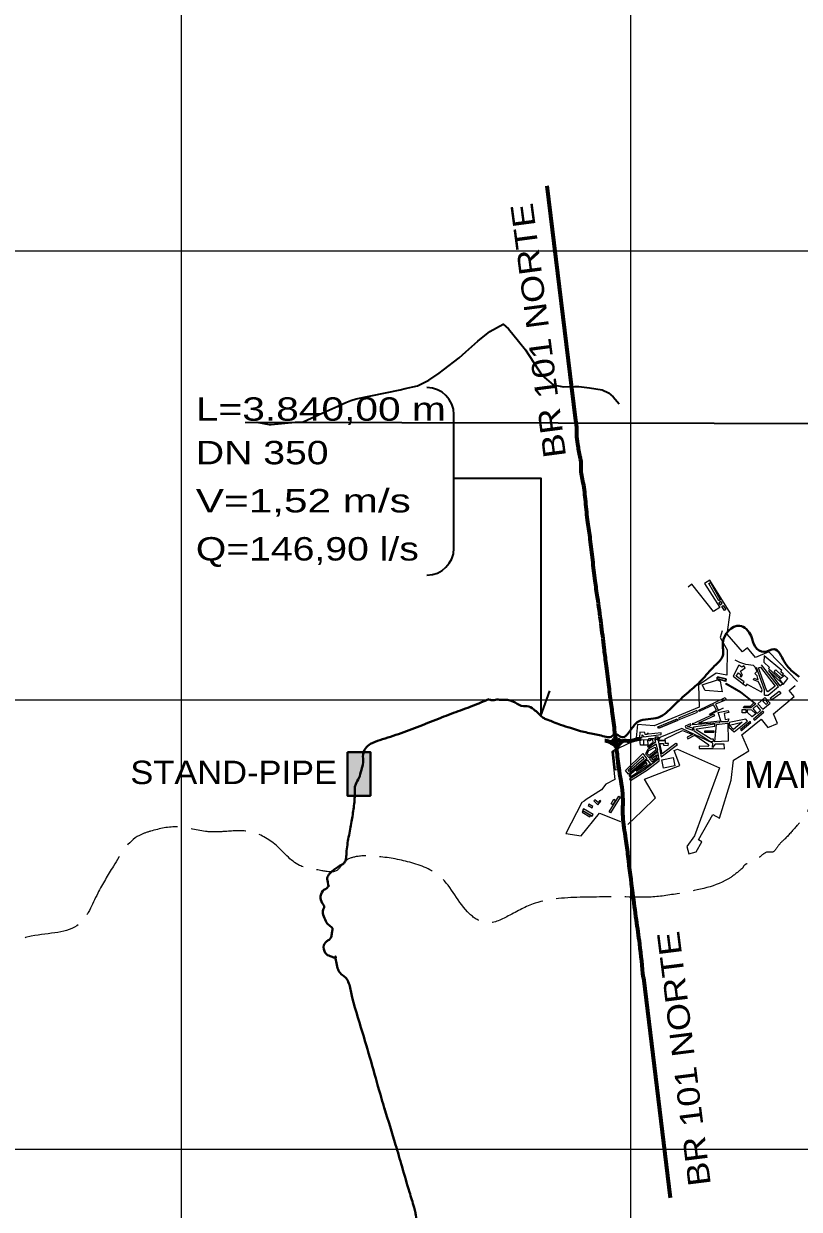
# Model space of a CAD drawing. Extents: x 0 to 1772, y 0 to 1188.
# Drawn here: x 975.1 to 1085.1, y 181.7 to 349.8 of the extents above; entities that cross this region are included whole.
import ezdxf

# ---------------------------------------------------------------- set-up
doc = ezdxf.new("R2010")
doc.units = 0
doc.header["$LTSCALE"] = 1.3
doc.linetypes.add('DOT_DASHED', pattern=[7.7, 5, -1.2, 0.3, -1.2])
doc.linetypes.add('LONG_DASHED', pattern=[7.5, 6, -1.5])
for name, color, linetype, lineweight in [('1', 7, 'DOT_DASHED', 13), ('3', 7, 'Continuous', 35), ('4', 7, 'Continuous', 13), ('5', 7, 'LONG_DASHED', 25), ('6', 7, 'Continuous', 40), ('63', 7, 'Continuous', 25), ('8', 7, 'Continuous', 35), ('9', 7, 'Continuous', 40)]:
    doc.layers.add(name, color=color, linetype=linetype, lineweight=lineweight)

msp = doc.modelspace()

# ---------------------------------------------------------------- hatches: boundary and pattern name
at = {"layer": '8'}
msp.add_hatch(color=256, dxfattribs=at).paths.add_polyline_path([(1021.023, 246.501), (1024.288, 246.501), (1024.288, 240.322), (1021.023, 240.322)])

# ---------------------------------------------------------------- linework, layer by layer
at = {"layer": '1', "linetype": 'Continuous'}
for p, q in [((1061.503, 248.025), (1059.413, 247.021)), ((1063.076, 247.499), (1062.565, 247.489)), ((1063.077, 247.49), (1063.066, 248.276))]:
    msp.add_line(p, q, dxfattribs=at)
for points in [[(1084.845, 256.515), (1080.766, 260.748), (1078.897, 259.943), (1077.745, 261.289), (1077.072, 260.713), (1074.895, 263.256), (1075.311, 266.276), (1072.428, 270.913), (1071.673, 270.444), (1073.816, 266.997), (1072.925, 266.443), (1069.86, 270.331), (1069.322, 269.907)], [(1074.171, 263.701), (1073.899, 262.776), (1074.877, 261.005), (1074.813, 257.409), (1073.315, 257.704), (1070.801, 255.998), (1070.91, 252.877), (1064.512, 250.229), (1062.144, 250.422), (1061.99, 248.528)], [(1079.72, 255.025), (1079.838, 255.321), (1079.338, 256.468), (1078.592, 256.773), (1078.689, 257.009), (1079.277, 256.769), (1079.111, 257.307), (1078.779, 257.649), (1079.121, 257.981), (1078.811, 258.62), (1078.586, 258.773), (1077.522, 258.923), (1076.694, 259.193), (1075.995, 259.546)], [(1079.72, 255.025), (1077.677, 256.124), (1077.547, 255.881), (1077.078, 256.133), (1077.263, 256.478), (1076.14, 257.277), (1076.471, 257.742), (1076.767, 257.532), (1076.73, 257.22), (1076.877, 257.202), (1077.072, 257.433), (1076.787, 257.964), (1077.434, 258.474), (1077.222, 258.743), (1076.953, 258.531), (1076.513, 258.826), (1075.727, 257.276), (1077.134, 256.205)], [(1080.178, 254.599), (1080.176, 255.332), (1079.029, 258.521)], [(1080.178, 254.599), (1080.706, 254.601), (1082.145, 255.826), (1079.732, 258.906)], [(1060.791, 236.222), (1060.791, 236.222), (1062.754, 238.124), (1064.717, 240.026), (1063.139, 242.666), (1068.167, 244.602), (1067.354, 246.715), (1067.838, 246.901), (1073.783, 244.253), (1070.229, 234.608), (1069.175, 233.101), (1069.451, 232.077), (1070.475, 232.353), (1071.289, 233.791), (1070.803, 234.066), (1072.838, 237.661), (1073.765, 237.137), (1075.461, 242.516), (1075.76, 245.352), (1077.94, 246.691), (1076.977, 248.977), (1079.701, 251.172), (1080.631, 250.017), (1081.989, 250.564), (1081.443, 251.922), (1084.367, 254.397), (1083.652, 255.241), (1084.496, 255.955)], [(1059.065, 246.87), (1058.542, 246.544), (1058.928, 242.628), (1057.684, 241.951), (1057.063, 241.176), (1054.899, 239.772), (1054.583, 239.567), (1054.267, 239.362), (1052.023, 234.949), (1054.192, 234.631), (1056.774, 237.832), (1059.743, 236.643)]]:
    msp.add_lwpolyline(points, dxfattribs=at)
for points in [[(1072.492, 270.562), (1073.901, 268.105), (1073.678, 267.977), (1072.269, 270.434)], [(1074.167, 267.618), (1073.963, 267.882), (1073.699, 267.678), (1073.903, 267.414)], [(1074.33, 267.313), (1074.698, 266.745), (1074.489, 266.61), (1074.122, 267.179)], [(1082.626, 258.064), (1080.141, 260.172), (1080.083, 259.277), (1080.898, 258.527), (1080.741, 258.357), (1082.245, 256.973), (1082.384, 257.124), (1081.538, 257.903), (1081.772, 258.157), (1082.669, 257.332), (1082.872, 257.553), (1082.499, 257.896)], [(1080.461, 255.292), (1079.334, 258.481), (1079.582, 258.569), (1081.678, 255.865), (1080.653, 255.071)], [(1080.757, 258.059), (1082.348, 255.908), (1082.733, 256.192)], [(1083.014, 257.353), (1082.305, 256.823), (1082.836, 256.113), (1083.483, 256.928)], [(1074.175, 255.056), (1071.772, 255.243), (1071.323, 256.056), (1073.492, 256.761), (1073.88, 256.549)], [(1074.692, 256.916), (1073.498, 257.194), (1073.44, 256.944), (1074.634, 256.667)], [(1073.451, 256.846), (1073.45, 257.146), (1074.731, 256.915), (1074.664, 256.542)], [(1077.278, 253.011), (1078.192, 253.014), (1078.635, 253.486), (1076.789, 254.92), (1074.668, 256.143), (1074.753, 256.29), (1076.785, 255.118), (1078.949, 253.33), (1078.219, 252.779), (1077.174, 252.789)], [(1072.381, 251.898), (1072.381, 251.898), (1073.36, 252.463), (1072.938, 253.193), (1070.917, 252.286), (1070.847, 252.442), (1074.569, 254.272), (1074.75, 253.905), (1073.239, 253.313), (1073.576, 252.454), (1074.301, 252.738), (1072.421, 251.78)], [(1080.959, 253.446), (1080.2, 254.263), (1079.235, 253.367), (1079.954, 252.592)], [(1081.196, 253.911), (1080.992, 254.175), (1082.237, 255.137), (1082.482, 254.821)], [(1068.087, 251.11), (1070.658, 252.172), (1070.568, 252.389), (1067.997, 251.327)], [(1074.959, 250.807), (1074.005, 250.804), (1073.609, 252.111), (1075.032, 252.403), (1075.092, 252.111), (1074.429, 251.975), (1074.605, 251.114), (1075.11, 251.218)], [(1077.018, 252.068), (1077.016, 252.552), (1077.501, 252.554), (1077.502, 252.069)], [(1078.421, 251.525), (1077.737, 252.144), (1077.773, 252.554), (1078.346, 252.504), (1078.916, 251.937)], [(1079.127, 251.987), (1078.542, 252.706), (1079.04, 253.111), (1079.621, 252.397)], [(1078.745, 251.042), (1080.069, 252.189), (1079.946, 252.331), (1078.622, 251.184)], [(1080.426, 253.27), (1079.928, 253.753), (1080.275, 253.903), (1080.649, 253.519)], [(1067.876, 250.969), (1065.142, 249.859), (1065.039, 250.113), (1067.773, 251.223)], [(1067.838, 250.987), (1065.204, 249.907), (1065.117, 250.119), (1067.751, 251.2)], [(1069.961, 250.506), (1072.952, 251.897), (1073.071, 251.641), (1070.808, 250.588), (1073.821, 250.963), (1073.781, 250.658), (1070.023, 250.352), (1070.002, 250.605)], [(1073.128, 247.969), (1073.344, 250.41), (1074.989, 250.598), (1074.997, 248.056)], [(1075.125, 250.037), (1075.884, 249.381), (1077.741, 250.89), (1077.525, 251.156), (1075.136, 250.696)], [(1075.796, 249.704), (1075.211, 250.336), (1077.022, 250.776)], [(1077, 249.646), (1078.25, 250.705), (1078.119, 250.86), (1076.742, 249.694), (1076.895, 249.514)], [(1065.503, 249), (1065.503, 249.247), (1063.731, 249.036), (1063.717, 249.154), (1063.514, 249.13), (1063.528, 249.018), (1063.235, 248.983), (1063.2, 249.276), (1062.469, 249.313), (1062.432, 248.582), (1062.819, 248.562), (1062.839, 248.949), (1063.015, 248.786), (1063.015, 248.654)], [(1074.462, 247.614), (1073.175, 247.611), (1072.802, 247.141), (1072.847, 247.774), (1068.441, 249.869), (1065.332, 248.595), (1065.053, 248.149), (1066.106, 248.105), (1066.106, 248.105), (1066.105, 248.386), (1066.105, 248.386), (1068.536, 249.565), (1069.965, 249.007), (1069.194, 248.606), (1069.314, 248.374), (1070.306, 248.89), (1072.286, 247.538), (1072.137, 247.319), (1070.906, 247.346), (1070.899, 247.04), (1072.876, 246.996), (1074.508, 246.959)], [(1069.986, 249.611), (1069.985, 249.882), (1069.267, 250.113), (1069.771, 250.347), (1069.682, 250.538), (1068.906, 250.177), (1069.011, 249.952)], [(1072.936, 248.048), (1072.935, 248.359), (1072.625, 248.358), (1070.49, 249.651), (1070.591, 249.818), (1073.143, 250.163), (1073.104, 250.454), (1070.105, 250.049), (1070.169, 249.574), (1072.471, 248.027)], [(1071.719, 249.527), (1073.006, 249.531), (1073.006, 249.297), (1071.719, 249.293)], [(1062.565, 247.489), (1062.481, 248.256), (1063.585, 248.293), (1063.611, 247.491)], [(1065.03, 246.781), (1064.818, 247.653), (1063.642, 246.875), (1063.3, 246.247), (1063.768, 245.745)], [(1064.772, 246.768), (1063.792, 246.003), (1063.544, 246.321), (1063.777, 246.74), (1064.648, 247.222)], [(1063.773, 248.103), (1063.772, 248.414), (1064.568, 248.416), (1064.704, 247.92), (1063.704, 247.152), (1063.575, 247.319), (1064.368, 247.928), (1064.331, 248.24), (1063.967, 248.24), (1063.967, 248.087), (1063.758, 248.087)], [(1064.838, 248.206), (1064.68, 248.651), (1065.125, 248.652)], [(1067.815, 247.563), (1067.617, 247.744), (1065.668, 246.244), (1065.351, 247.745), (1065.87, 247.722), (1065.86, 247.492), (1066.528, 247.462), (1066.54, 247.732), (1066.134, 247.75), (1066.153, 248.156), (1065.097, 248.203), (1065.496, 245.823)], [(1059.022, 243.961), (1058.781, 246.553), (1059.039, 246.577), (1059.28, 243.985)], [(1060.878, 243.364), (1060.483, 243.903), (1062.895, 246.332), (1063.462, 245.572)], [(1060.975, 243.745), (1060.839, 243.941), (1062.908, 245.89), (1063.044, 245.558)], [(1065.231, 245.282), (1065.23, 245.585), (1063.086, 243.96), (1061.039, 242.676), (1061.163, 242.478), (1063.597, 244.006)], [(1065.205, 245.761), (1065.055, 246.56), (1063.879, 245.573), (1064.245, 245.137)], [(1064.861, 245.748), (1064.371, 245.378), (1064.212, 245.588), (1064.908, 246.113)], [(1065.864, 244.223), (1065.621, 245.403), (1067.205, 245.728), (1067.447, 244.549)], [(1063.548, 245.4), (1063.992, 244.799), (1061.161, 242.959), (1060.996, 243.213)], [(1061.994, 243.81), (1063.538, 244.773), (1063.367, 245.047)], [(1055.156, 238.928), (1055.723, 238.593), (1055.844, 238.798), (1055.276, 239.133)], [(1055.98, 239.581), (1056.556, 239.025), (1056.967, 239.546), (1056.823, 239.66), (1056.576, 239.347), (1056.099, 239.723)], [(1058.14, 238.033), (1059.498, 240.244), (1059.707, 240.116), (1058.349, 237.905)], [(1058.409, 239.148), (1058.785, 239.821), (1059.022, 239.689), (1058.646, 239.016)], [(1054.297, 237.979), (1055.412, 237.31), (1055.526, 237.498), (1054.411, 238.168)], [(1055.852, 237.648), (1054.485, 238.442), (1054.362, 238.23), (1055.729, 237.436)]]:
    msp.add_lwpolyline(points, close=True, dxfattribs=at)
at = {"layer": '3'}
for points in [[(1139.418, 292.958), (1006.614, 293.247), (1008.192, 293.315), (1009.946, 292.988), (1010.201, 292.983), (1013.605, 293.316), (1014.771, 293.369), (1017.552, 294.641), (1019.654, 295.559), (1020.812, 296.089), (1021.528, 296.357), (1022.255, 296.595), (1028.496, 297.874), (1029.236, 298.067), (1030.977, 298.455), (1032.573, 299.254), (1034.033, 300.279), (1034.654, 300.724), (1036.861, 302.453), (1037.829, 303.282), (1039.544, 304.804), (1041.226, 306.17), (1043.119, 307.223), (1043.865, 306.529), (1045.279, 304.788), (1046.297, 303.579), (1048.63, 299.928)], [(1139.418, 292.958), (1006.614, 293.247), (1008.192, 293.315), (1009.946, 292.988), (1010.201, 292.983), (1013.605, 293.316), (1014.771, 293.369), (1017.552, 294.641), (1019.654, 295.559), (1020.812, 296.089), (1021.528, 296.357), (1022.255, 296.595), (1028.496, 297.874), (1029.236, 298.067), (1030.977, 298.455), (1032.573, 299.254), (1034.033, 300.279), (1034.654, 300.724), (1036.861, 302.453), (1037.829, 303.282), (1039.544, 304.804), (1041.226, 306.17), (1043.119, 307.223), (1043.865, 306.529), (1045.279, 304.788), (1046.297, 303.579), (1048.63, 299.928)], [(1048.63, 299.928), (1050.182, 298.607), (1051.686, 298.33), (1053.214, 298.386), (1053.85, 298.353), (1055.371, 298.196), (1057.131, 297.904), (1058.048, 297.458), (1058.732, 296.886), (1059.569, 295.925)], [(1048.63, 299.928), (1050.182, 298.607), (1051.686, 298.33), (1053.214, 298.386), (1053.85, 298.353), (1055.371, 298.196), (1057.131, 297.904), (1058.048, 297.458), (1058.732, 296.886), (1059.569, 295.925)]]:
    msp.add_lwpolyline(points, dxfattribs=at)
at = {"layer": '4', "lineweight": 70}
for p, q in [((1053.374, 293.92), (1049.343, 326.851)), ((1062.992, 214.486), (1066.783, 183.302))]:
    msp.add_line(p, q, dxfattribs=at)
for points in [[(1059.249, 246.974), (1058.922, 249.644), (1058.59, 252.299), (1058.417, 253.395), (1058.1, 256.112), (1057.706, 259.091), (1057.437, 261.298), (1057.008, 264.756), (1056.496, 268.489), (1056.155, 270.801), (1055.812, 273.781), (1055.47, 276.706), (1055.129, 279.102), (1054.814, 282.027), (1054.472, 284.701), (1054.159, 286.762), (1054.156, 287.778), (1054.019, 288.375), (1053.721, 290.194), (1053.541, 291.596), (1053.538, 292.612), (1053.374, 293.92)], [(1059.245, 246.912), (1059.083, 247.313), (1058.526, 247.744), (1058.094, 247.989), (1057.547, 248.109)], [(1058.246, 247.93), (1058.759, 248.175), (1059.046, 248.627)], [(1059.943, 247.986), (1059.389, 248.257), (1059.015, 248.574)], [(1062.992, 214.486), (1062.48, 219.286), (1062.008, 222.699), (1061.499, 226.502), (1060.843, 231.733), (1060.528, 234.21), (1060.11, 237.363), (1060.102, 240.129), (1059.599, 243.835), (1059.264, 246.517), (1059.262, 247.097), (1059.422, 247.422), (1059.868, 247.917), (1060.114, 248.088), (1060.962, 248.091), (1062.226, 248.372), (1062.689, 248.374)]]:
    msp.add_spline(points, degree=3, dxfattribs=at)
at = {"layer": '5'}
for points in [[(1098.436, 246.938), (1097.807, 246.034), (1097.288, 245.694), (1096.079, 245.469), (1093.569, 245.019), (1092.282, 244.807), (1090.825, 244.802), (1089.615, 244.799), (1088.498, 244.379), (1087.889, 243.934), (1087.489, 242.825), (1087.147, 241.019), (1086.658, 239.259), (1086.205, 237.957), (1085.595, 237.012), (1084.774, 236.085), (1083.091, 234.22), (1082.101, 233.196), (1081.312, 232.334), (1080.641, 232.332), (1079.69, 231.779), (1078.793, 231.118), (1077.761, 230.712), (1077.198, 230.32), (1077.038, 230.038)], [(1077.038, 230.038), (1075.377, 228.735), (1068.326, 226.516), (1064.082, 225.946), (1061.885, 225.939), (1054.455, 225.917), (1047.631, 225.056), (1043.838, 223.262), (1040.576, 222.301), (1038.376, 223.542), (1034.205, 228.819), (1029.866, 230.886), (1025.174, 231.704), (1022.373, 231.696), (1020.616, 230.946), (1019.536, 229.723), (1017.235, 229.716), (1014.255, 230.43), (1010.727, 233.446), (1007.021, 235.242), (1003.502, 235.231), (1001.155, 235.224), (997.002, 235.89), (993.124, 235.291), (991.546, 234.699), (987.842, 230.305)], [(987.842, 230.305), (985.628, 226.476), (982.964, 222.096), (976.206, 220.383), (964.658, 218.233), (961.115, 225.134), (959.277, 227.385), (956.197, 220.747), (950.998, 215.794), (940.713, 215.764), (940.699, 220.277), (940.263, 220.276), (938.015, 222.808), (938.024, 219.564), (934.079, 219.552), (928.422, 226.588), (925.891, 224.888), (927.742, 218.264), (927.76, 212.34), (922.124, 212.323), (915.354, 214.56), (900.56, 214.516), (895.639, 215.427), (893.532, 217.905), (890.518, 220.428), (888.219, 223.335), (886.162, 225.239), (883.344, 225.947), (879.87, 226.373)]]:
    msp.add_spline(points, degree=3, dxfattribs=at)
at = {"layer": '6'}
for points in [[(1057.728, 248.682), (1058.416, 248.684), (1058.866, 249.018), (1059.608, 248.789), (1059.969, 248.63), (1061.178, 249.606), (1062.295, 250.832), (1065.134, 251.415), (1067.196, 253.001), (1069.4, 255.019), (1071.232, 256.691), (1073.091, 258.737), (1074.264, 260.177), (1074.258, 262.073), (1076.633, 264.436), (1078.274, 262.976), (1078.848, 261.465), (1080.116, 260.722), (1081.52, 261.108), (1082.982, 259.325), (1084.13, 257.956), (1085.097, 257.196)], [(1041.149, 254.036), (1038.771, 253.058), (1036.059, 252.054), (1034.707, 251.54), (1028.651, 249.197), (1025.623, 248.201), (1024.314, 247.676), (1023.578, 247.021), (1023.247, 246.17), (1023.25, 245.014), (1023.009, 243.984), (1022.662, 242.814), (1022.204, 241.971), (1022.064, 240.421), (1021.892, 238.398), (1021.579, 236.391), (1021.155, 234.179), (1020.878, 231.938), (1020.762, 231.103), (1020.627, 230.847), (1020.273, 230.57), (1019.555, 230.136), (1019.049, 229.754), (1018.548, 229.307), (1018.154, 228.63), (1018.32, 227.7), (1018.376, 227.505), (1018.378, 227.512), (1018.196, 227.316), (1017.69, 226.955), (1017.234, 226.071), (1017.452, 225.1), (1017.729, 224.635), (1017.739, 224.593), (1017.598, 224.165), (1017.689, 223.194), (1018.063, 222.354), (1018.59, 221.822), (1018.868, 221.585), (1018.909, 221.477), (1018.85, 221.028), (1018.759, 220.376), (1018.667, 220.158), (1018.515, 219.962), (1018.114, 219.686), (1017.662, 218.857), (1018.054, 217.838), (1018.875, 217.462), (1019.41, 217.389), (1019.375, 217.467), (1019.519, 216.345), (1019.775, 215.523), (1020.332, 214.855), (1020.828, 214.477), (1021.066, 214.114), (1021.558, 212.422), (1023.165, 206.741), (1024.546, 202.008), (1025.868, 197.355), (1026.305, 195.882)], [(1057.728, 248.682), (1055.833, 249.104), (1053.806, 249.56), (1052.646, 249.928), (1051.238, 250.393), (1050.269, 250.765), (1049.457, 251.075), (1048.914, 251.31), (1048.445, 251.657), (1048.054, 252.031), (1047.475, 252.553), (1046.481, 253.027), (1045.982, 253.026), (1044.833, 253.536), (1043.34, 253.934), (1042.804, 253.933), (1042.021, 253.931), (1041.273, 253.928), (1041.154, 254.043)], [(1026.288, 195.944), (1027.862, 190.814), (1028.772, 187.696), (1029.831, 184.1), (1030.476, 181.92), (1030.672, 181.139), (1030.727, 180.863), (1030.173, 177.991), (1029.567, 174.805), (1028.509, 169.395), (1027.251, 162.313), (1026.888, 160.509), (1026.803, 160.245), (1026.315, 159.545), (1025.404, 158.587), (1024.533, 157.71), (1023.812, 156.941), (1023.307, 156.415), (1021.965, 155.073), (1018.167, 151.123), (1015.097, 147.953), (1012.556, 145.333), (1011.612, 144.176), (1010.783, 143.075), (1010.549, 142.744), (1009.148, 142.985)]]:
    msp.add_spline(points, degree=3, dxfattribs=at)
at = {"layer": '63', "lineweight": 13}
for p, q in [((997.519, 62.735), (997.519, 419.523)), ((1061.231, 62.735), (1061.231, 419.523)), ((1175.913, 317.583), (487.822, 317.583)), ((1175.913, 253.871), (487.822, 253.871)), ((1175.913, 190.159), (487.822, 190.159))]:
    msp.add_line(p, q, dxfattribs=at)
at = {"layer": '8'}
msp.add_line((1036.127, 275.423), (1036.127, 294.379), dxfattribs=at)
msp.add_lwpolyline([(1036.127, 285.38), (1048.477, 285.38), (1048.477, 251.628), (1049.743, 255.194)], dxfattribs=at)
at = {"layer": '8', "lineweight": 40}
msp.add_lwpolyline([(1021.023, 246.501), (1024.288, 246.501), (1024.288, 240.322), (1021.023, 240.322)], close=True, dxfattribs=at)
at = {"layer": '8'}
for centre, start, end in [((1032.305, 294.379), 0, 90), ((1032.305, 294.379), 0, 90), ((1032.305, 294.379), 0, 90), ((1032.305, 275.423), 270, 0)]:
    msp.add_arc(centre, 3.823, start, end, dxfattribs=at)

# ---------------------------------------------------------------- texts
at = {"layer": '8', "width": 1.2}
for rotation, p in [(97.529, (1052.047, 288.471)), (97.128, (1072.57, 185.155))]:
    msp.add_text('BR 101 NORTE', height=3.186, rotation=rotation, dxfattribs=at).set_placement(p)
at = {"layer": '8'}
for s, width, p in [('L=3.840,00 m', 1.3, (999.543, 293.509)), ('DN 350', 1.25, (999.543, 287.329)), ('V=1,52 m/s', 1.35, (999.543, 280.506)), ('Q=146,90 l/s', 1.25, (999.543, 273.682)), ('STAND-PIPE', 1.1, (990.254, 241.97))]:
    msp.add_text(s, height=3.319, dxfattribs=dict(at, width=width)).set_placement(p)
at = {"layer": '9'}
msp.add_text('MAMANGUAPE', height=3.823, rotation=0.17, dxfattribs=at).set_placement((1077.26, 241.408))

doc.saveas('drawing.dxf')
